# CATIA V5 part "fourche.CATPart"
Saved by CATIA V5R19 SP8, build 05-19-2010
Part number: fourche
Bounding box of the stored display mesh (mm): x -45 to 45, y -16.228 to 17.401, z -14.888 to 291.666
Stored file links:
  G:\EU_thinkMotion\CFAO_2010\SIL_groupe1\SIL_groupe1\A reprendre\scador\monocycle\fourche.CATPart
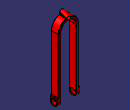
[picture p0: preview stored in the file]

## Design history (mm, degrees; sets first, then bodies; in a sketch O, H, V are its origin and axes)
Parameters
  rayon_roue = 200 mm
Set1
  Point1: (0, 0, 0)
  Point2: (0, 10, 275 {= rayon_roue +65mm+10mm})
  Line1: type Normal, RefPoint Point2, RefSkin yz-plane, Start 0, End 50
  Plane1: type Angle, RefPlane zx-plane, Direction Line1, Angle -20
  Line2: type Normal, RefPoint Point1, RefSkin yz-plane, Start 0, End 50
  Point3: (30, 20, 0)
Body1 (main body)
  Sketch1 on zx-plane, origin (0, 0, 0), H (-1, 0, 0), V (0, 0, 1)
    line L1 (-40, 235) -> (-40, 16)
    line L2 (-40, -16) -> (-30, -16)
    line L3 (-30, -16) -> (-30, 235)
    arc A1 centre (0, 235) radius 30 from (-30, 235) to (30, 235) cw
    point P5 (0, 235)
    line L4 (30, 235) -> (30, -16)
    line L5 (30, -16) -> (40, -16)
    line L6 (40, 16) -> (40, 235)
    arc A2 centre (0, 235) radius 40 from (40, 235) to (-40, 235) ccw
    line L7 (40, -16) -> (45, -16)
    line L8 (45, -16) -> (45, 16)
    line L9 (45, 16) -> (40, 16)
    line L10 (-40, -16) -> (-45, -16)
    line L11 (-45, -16) -> (-45, 16)
    line L12 (-45, 16) -> (-40, 16)
    point P15 (-45, 16)
    distance O A1 = 265 {= rayon_roue +65mm}
    distance L4 L6 = 10
    distance A1 A2 = 10
    distance A1 P5 = 30
    distance L3 L1 = 10
    distance H L5 = 16
    distance H L2 = 16
    distance L6 L8 = 5
    distance L11 L1 = 5
    distance L7 L9 = 32
    vertical: L1 V, L3 V, L6 V, L8 V, L11 V
    horizontal: L2 H, L5 H, L7 H, L9 H, L10 H, L12 H
    tangency: A1 L3, L4 A1, A2 L1, A2 L6
    coincidence: P15 L9
  Pad1: profile Sketch1, direction (0, 1, 0), length 15, opposite side length 15
  Sketch2 on face of Pad1 from Sketch1.L11, origin (45, 2.2459, 2.3956), H (0, 1, 0), V (0, 0, 1)
    point P1 (-2.2459, -2.3956)
    construction circle A1 centre (0, 0) radius 10
    reference projected line E1 (12.7541, 13.6044) -> (12.7541, -18.3956) from edge [face of Pad1 from Sketch1.L11 | end face of Pad1]
    reference projected line E2 (-17.2459, -18.3956) -> (12.7541, -18.3956) from edge [face of Pad1 from Sketch1.L10 | face of Pad1 from Sketch1.L11]
    radius A1 = 10
    distance P1 E1 = 15
    distance P1 E2 = 16
  Hole1: placed by Sketch2, at (45, 0, 0) direction (-1, 0, 0), diameter 20, through (limit type 3)
  Sketch3 on face of Pad1 from Sketch1.L11, origin (45, 0, -16), H (0, 0, 1), V (0, 1, 0)
    arc A1 centre (16.1124, 0) radius 15 from (16.1124, 15) to (16.1124, -15) ccw
    point P1 (16.1124, 0)
    reference projected line E1 (0, 15) -> (32, 15) from edge [face of Pad1 from Sketch1.L8 | end face of Pad1]
    reference projected line E2 (0, -15) -> (32, -15) from edge [start face of Pad1 | face of Pad1 from Sketch1.L8]
    line L1 (16.1124, 15) -> (0, 15)
    point P4 (0, 15)
    point P5 (0, -15)
    line L2 (0, -15) -> (16.1124, -15)
    reference projected line E3 (0, -15) -> (32, -15) from edge [start face of Pad1 | face of Pad1 from Sketch1.L8]
    reference projected line E4 (0, 15) -> (32, 15) from edge [face of Pad1 from Sketch1.L8 | end face of Pad1]
    line L3 (0, 15) -> (0, -15)
    point P6 (0, 15)
    point P7 (0, -15)
    reference projected line E5 (0, -15) -> (0, 15) from edge [face of Pad1 from Sketch1.L8 | face of Pad1 from Sketch1.L7]
    coincidence: P1 H, P4 V, L2 E3, L1 E4, P6 L1, P7 L2, L3 E5, P4 P6, P5 P7
    tangency: A1 E1, A1 E2, L1 A1, L2 A1
    vertical: L3 V
  Pocket1: profile Sketch3, direction (-1, 0, 0), length 100
  Sketch4 on Plane1, origin (0, -79.5531, 28.955), H (-1, 0, 0), V (0, 0.342, 0.9397)
    circle A1 centre (0, 261.8357) radius 7
    point P1 (0, 261.8357)
    circle A2 centre (0, 261.8357) radius 9
    reference projected point E1 (0, 261.8357) from Point2
    radius A1 = 7
    radius A2 = 9
    coincidence: P1 V, P1 E1
  Pad2: profile Sketch4, direction (0, 0.9397, -0.342), length 5, opposite side length 25
  Sketch5 on end face of Pad2, origin (0, -74.8546, 27.2449), H (-1, 0, 0), V (0, 0.342, 0.9397)
    circle A1 centre (0, 261.8357) radius 7
    point P1 (0, 261.8357)
    reference projected point E1 (0, 261.8357) from Point2
    radius A1 = 7
    coincidence: P1 V, E1 P1
  Pocket2: profile Sketch5, direction (0, -0.9397, 0.342), length 50, opposite side length 50
  Fillet1: radius 2, on face of Pad1 from Sketch1.L1
  Fillet2: radius 2, on edge [face of Pad2 from Sketch4.A2 | face of Pad1 from Sketch1.A2]; edge [face of Pad1 from Sketch1.L6 | end face of Pad1]; edge [start face of Pad1 | face of Pad1 from Sketch1.L6]; edge [face of Pad1 from Sketch1.L6 | face of Pad1 from Sketch1.L9]
  Fillet3: radius 2, on face of Pad1 from Sketch1.L8
  Fillet4: radius 2, on face of Pad1 from Sketch1.L11
  Fillet5: radius 2, on edge [start face of Pad1 | face of Pad1 from Sketch1.L4]; edge [face of Pad1 from Sketch1.L4 | end face of Pad1]
  Fillet6: radius 2, on edge [face of Pad1 from Sketch1.L4 | face of Hole1]
  Fillet7: radius 2, on edge [face of Pad1 from Sketch1.L3 | face of Hole1]
  Fillet8: radius 1, on edge [start face of Pad2 | face of Pad2 from Sketch4.A2]
  Fillet9: radius 1, on edge [face of Pad2 from Sketch4.A1 | start face of Pad2]
  Fillet10: radius 1, on edge [face of Pad2 from Sketch4.A2 | end face of Pad2]
  Fillet11: radius 1, on edge [end face of Pad2 | face of Pad2 from Sketch4.A1]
